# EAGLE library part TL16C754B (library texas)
QUAD UART WITH 64-BYTE FIFO Source: http://focus.ti.com/lit/ds/symlink/tl16c754b.pdf
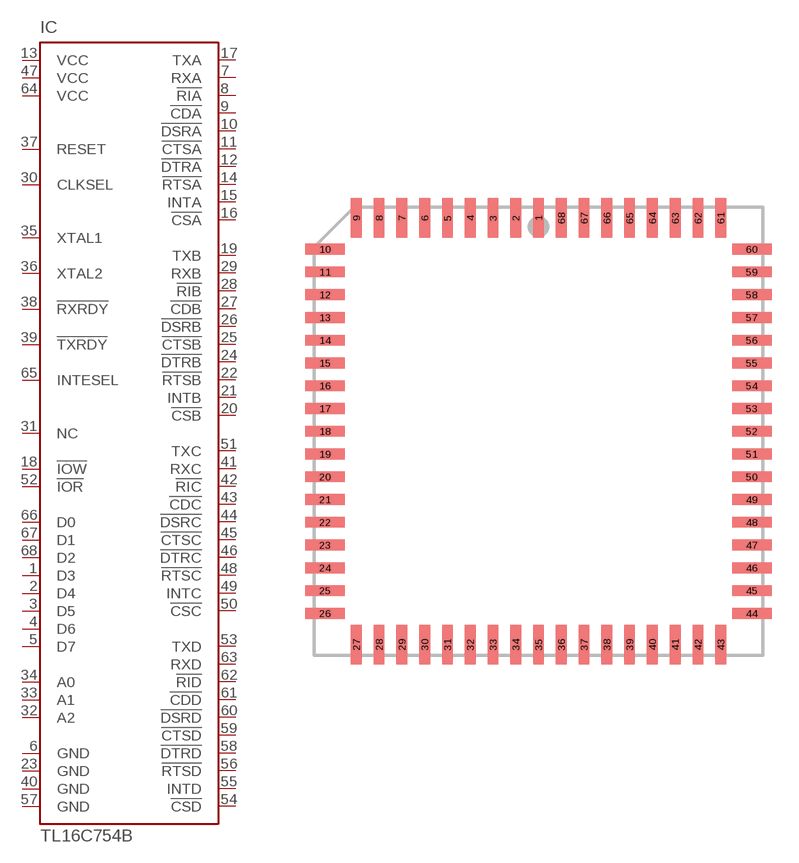
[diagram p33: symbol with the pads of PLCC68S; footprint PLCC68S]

Designator prefix IC

## TL16C754B (MPN: TL16C754BFN; OC_FARNELL: 1659627; OC_NEWARK: 12P7902)  [PLCC68S]
1  D3
2  D4
3  D5
4  D6
5  D7
6  GND
7  RXA
8  !RIA
9  !CDA
10  !DSRA
11  !CTSA
12  !DTRA
13  VCC
14  !RTSA
15  INTA
16  !CSA
17  TXA
18  !IOW
19  TXB
20  !CSB
21  INTB
22  !RTSB
23  GND
24  !DTRB
25  !CTSB
26  !DSRB
27  !CDB
28  !RIB
29  RXB
30  CLKSEL
31  NC
32  A2
33  A1
34  A0
35  XTAL1
36  XTAL2
37  RESET
38  !RXRDY
39  !TXRDY
40  GND
41  RXC
42  !RIC
43  !CDC
44  !DSRC
45  !CTSC
46  !DTRC
47  VCC
48  !RTSC
49  INTC
50  !CSC
51  TXC
52  !IOR
53  TXD
54  !CSD
55  INTD
56  !RTSD
57  GND
58  !DTRD
59  !CTSD
60  !DSRD
61  !CDD
62  !RID
63  RXD
64  VCC
65  INTESEL
66  D0
67  D1
68  D2

## Footprint PLCC68S (pad centres in mm)
PLASTIC LEADED CHIP CARRIER square
smd 0.6 x 2.2: 1 0,11.9; 2 -1.27,11.9; 3 -2.54,11.9; 4 -3.81,11.9; 5 -5.08,11.9; 6 -6.35,11.9; 7 -7.62,11.9; 8 -8.89,11.9; 9 -10.16,11.9; 27 -10.16,-11.9; 28 -8.89,-11.9; 29 -7.62,-11.9; 30 -6.35,-11.9; 31 -5.08,-11.9; 32 -3.81,-11.9; 33 -2.54,-11.9; 34 -1.27,-11.9; 35 0,-11.9; 36 1.27,-11.9; 37 2.54,-11.9; 38 3.81,-11.9; 39 5.08,-11.9; 40 6.35,-11.9; 41 7.62,-11.9; 42 8.89,-11.9; 43 10.16,-11.9; 61 10.16,11.9; 62 8.89,11.9; 63 7.62,11.9; 64 6.35,11.9; 65 5.08,11.9; 66 3.81,11.9; 67 2.54,11.9; 68 1.27,11.9
smd 2.2 x 0.6: 10 -11.9,10.16; 11 -11.9,8.89; 12 -11.9,7.62; 13 -11.9,6.35; 14 -11.9,5.08; 15 -11.9,3.81; 16 -11.9,2.54; 17 -11.9,1.27; 18 -11.9,0; 19 -11.9,-1.27; 20 -11.9,-2.54; 21 -11.9,-3.81; 22 -11.9,-5.08; 23 -11.9,-6.35; 24 -11.9,-7.62; 25 -11.9,-8.89; 26 -11.9,-10.16; 44 11.9,-10.16; 45 11.9,-8.89; 46 11.9,-7.62; 47 11.9,-6.35; 48 11.9,-5.08; 49 11.9,-3.81; 50 11.9,-2.54; 51 11.9,-1.27; 52 11.9,0; 53 11.9,1.27; 54 11.9,2.54; 55 11.9,3.81; 56 11.9,5.08; 57 11.9,6.35; 58 11.9,7.62; 59 11.9,8.89; 60 11.9,10.16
